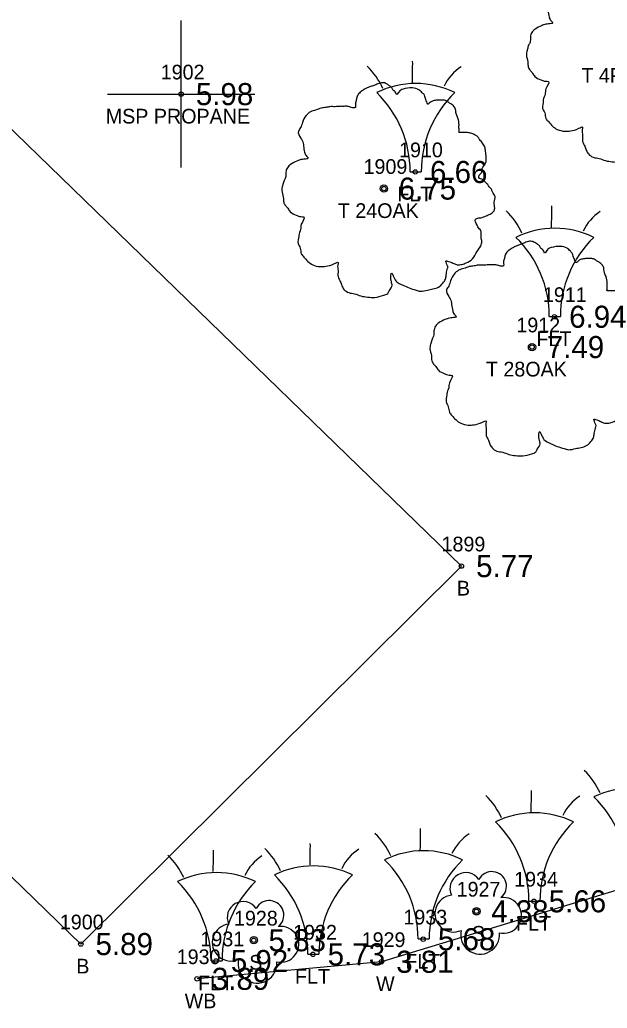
# Model space of a CAD drawing. Extents: x 2608598 to 2610682, y 641451 to 643526.
# Drawn here: x 2609191.3 to 2609231.3, y 642871.7 to 642938.9 of the extents above; entities that cross this region are included whole.
import ezdxf

# ---------------------------------------------------------------- set-up
doc = ezdxf.new("R2010")
doc.units = 0
for name, color, linetype in [('RD_EX_Bldg', 7, 'Continuous'), ('RD_EX_Bldg_txCode', 7, 'Continuous'), ('RD_EX_BldgApp', 7, 'Continuous'), ('RD_EX_BldgApp_txCode', 7, 'Continuous'), ('RD_EX_Misc', 7, 'Continuous'), ('RD_EX_Misc_txCode', 7, 'Continuous'), ('RD_EX_TX_Bldg_ELEV', 7, 'Continuous'), ('RD_EX_TX_BldgApp_ELEV', 7, 'Continuous'), ('RD_EX_TX_Misc_ELEV', 7, 'Continuous'), ('RD_EX_TX_VEG_ELEV', 7, 'Continuous'), ('RD_EX_VEG', 7, 'Continuous'), ('RD_EX_VEG_txCode', 7, 'Continuous'), ('RD_SMD_Locator', 7, 'Continuous')]:
    doc.layers.add(name, color=color, linetype=linetype)

msp = doc.modelspace()

# ---------------------------------------------------------------- linework, layer by layer
at = {"layer": 'RD_EX_Bldg'}
msp.add_lwpolyline([(2609131.739, 642937.949), (2609157.607, 642963.648), (2609221.367, 642901.728), (2609195.499, 642876.028), (2609131.739, 642937.949)], dxfattribs=at)
at = {"layer": 'RD_EX_BldgApp'}
for p, q in [((2609217.887, 642928.548), (2609218.637, 642928.548)), ((2609227.343, 642918.704), (2609228.093, 642918.704)), ((2609225.957, 642878.955), (2609226.707, 642878.955)), ((2609218.424, 642876.377), (2609219.174, 642876.377)), ((2609210.931, 642875.348), (2609211.681, 642875.348)), ((2609204.348, 642874.893), (2609205.098, 642874.893))]:
    msp.add_line(p, q, dxfattribs=at)
msp.add_lwpolyline([(2609259.329, 642906.089), (2609262.471, 642891.581), (2609238.117, 642881.572), (2609215.937, 642874.826), (2609203.404, 642873.665)], dxfattribs=at)
for centre, radius, start, end in [((2609211.569, 642932.191), 4.895, 24.32791, 46.26654), ((2609180.18, 642935.886), 37.876, 358.06712, 0.27154), ((2609223.15, 642932.941), 3.283, 123.29064, 154.48862), ((2609218.262, 642928.548), 5.997, 63.77943, 116.22057), ((2609210.387, 642928.548), 7.5, 0, 45.83662), ((2609226.137, 642928.548), 7.5, 134.16338, 180), ((2609221.026, 642922.347), 4.895, 24.32791, 46.26654), ((2609189.637, 642926.042), 37.876, 358.06712, 0.27154), ((2609232.607, 642923.097), 3.283, 123.29064, 154.48862), ((2609227.718, 642918.704), 5.997, 63.77943, 116.22057), ((2609219.843, 642918.704), 7.5, 0, 45.83662), ((2609235.593, 642918.704), 7.5, 134.16338, 180), ((2609226.338, 642884.294), 4.895, 24.32791, 46.26654), ((2609233.03, 642880.651), 5.997, 63.77943, 116.22057), ((2609219.639, 642882.597), 4.895, 24.32791, 46.26654), ((2609188.25, 642886.293), 37.876, 358.06712, 0.27154), ((2609231.22, 642883.348), 3.283, 123.29064, 154.48862), ((2609225.155, 642880.651), 7.5, 0, 45.83662), ((2609226.332, 642878.955), 5.997, 63.77943, 116.22057), ((2609218.457, 642878.955), 7.5, 0, 45.83662), ((2609234.207, 642878.955), 7.5, 134.16338, 180), ((2609212.106, 642880.019), 4.895, 24.32791, 46.26654), ((2609180.717, 642883.715), 37.876, 358.06712, 0.27154), ((2609223.687, 642880.77), 3.283, 123.29064, 154.48862), ((2609173.224, 642882.686), 37.876, 358.06712, 0.27154), ((2609198.03, 642878.536), 4.895, 24.32791, 46.26654), ((2609166.641, 642882.231), 37.876, 358.06712, 0.27154), ((2609209.611, 642879.286), 3.283, 123.29064, 154.48862), ((2609204.613, 642878.991), 4.895, 24.32791, 46.26654), ((2609216.194, 642879.741), 3.283, 123.29064, 154.48862), ((2609218.799, 642876.377), 5.997, 63.77943, 116.22057), ((2609211.306, 642875.348), 5.997, 63.77943, 116.22057), ((2609210.924, 642876.377), 7.5, 0, 45.83662), ((2609226.674, 642876.377), 7.5, 134.16338, 180), ((2609204.723, 642874.893), 5.997, 63.77943, 116.22057), ((2609203.431, 642875.348), 7.5, 0, 45.83662), ((2609219.181, 642875.348), 7.5, 134.16338, 180), ((2609196.848, 642874.893), 7.5, 0, 45.83662), ((2609212.598, 642874.893), 7.5, 134.16338, 180)]:
    msp.add_arc(centre, radius, start, end, dxfattribs=at)
at = {"layer": 'RD_EX_Misc'}
for p, q in [((2609202.317, 642928.823), (2609202.317, 642938.823)), ((2609197.317, 642933.823), (2609207.317, 642933.823))]:
    msp.add_line(p, q, dxfattribs=at)
at = {"layer": 'RD_EX_VEG'}
for centre, radius in [((2609216.103, 642927.4), 0.25), ((2609216.09, 642927.381), 0.0001), ((2609226.169, 642916.623), 0.25), ((2609226.156, 642916.604), 0.0001), ((2609222.392, 642878.257), 0.25), ((2609207.256, 642876.289), 0.25)]:
    msp.add_circle(centre, radius, dxfattribs=at)
for centre, radius, start, end in [((2609221.671, 642879.804), 1.084, 34.97629, 204.75602), ((2609223.437, 642879.959), 0.995, 308.76261, 152.04674), ((2609220.828, 642878.101), 1.257, 96.45179, 294.73401), ((2609206.535, 642877.836), 1.084, 34.97629, 204.75602), ((2609208.302, 642877.991), 0.995, 308.76261, 152.04674), ((2609224.231, 642877.978), 1.218, 256.56668, 98.10463), ((2609205.693, 642876.133), 1.257, 96.45179, 294.73401), ((2609209.096, 642876.01), 1.218, 256.56668, 98.10463), ((2609222.637, 642876.661), 1.318, 166.88266, 5.75893), ((2609207.502, 642874.693), 1.318, 166.88266, 5.75893)]:
    msp.add_arc(centre, radius, start, end, dxfattribs=at)
for points in [[(2609232.857, 642943.771), (2609232.557, 642943.796), (2609232.232, 642943.696), (2609231.982, 642943.596), (2609231.757, 642943.521), (2609231.532, 642943.421), (2609231.232, 642943.246), (2609231.008, 642943.046), (2609230.883, 642942.796), (2609230.833, 642942.571), (2609230.783, 642942.296), (2609230.783, 642942.121), (2609230.658, 642942.096), (2609230.508, 642942.121), (2609230.258, 642942.196), (2609230.008, 642942.196), (2609229.758, 642942.196), (2609229.408, 642942.171), (2609229.058, 642942.171), (2609228.784, 642942.121), (2609228.459, 642942.071), (2609228.084, 642941.946), (2609227.734, 642941.821), (2609227.434, 642941.572), (2609227.184, 642941.097), (2609227.059, 642940.747), (2609226.909, 642940.497), (2609227.059, 642940.047), (2609227.234, 642939.697), (2609227.259, 642939.497), (2609227.334, 642939.073), (2609227.434, 642938.848), (2609227.559, 642938.648), (2609227.484, 642938.623), (2609227.109, 642938.573), (2609226.809, 642938.473), (2609226.385, 642938.248), (2609226.16, 642938.023), (2609226.06, 642937.698), (2609226.035, 642937.348), (2609225.935, 642937.149), (2609225.86, 642936.874), (2609225.835, 642936.799), (2609225.785, 642936.474), (2609225.885, 642936.024), (2609225.91, 642935.674), (2609226.035, 642935.449), (2609226.185, 642935.274), (2609226.36, 642935.024), (2609226.759, 642934.8), (2609227.084, 642934.7), (2609227.284, 642934.675), (2609227.109, 642934.175), (2609227.059, 642933.825), (2609226.934, 642933.425), (2609226.934, 642933.35), (2609226.884, 642932.875), (2609227.034, 642932.55), (2609227.109, 642932.176), (2609227.284, 642931.951), (2609227.559, 642931.651), (2609227.884, 642931.426), (2609228.384, 642931.301), (2609228.784, 642931.326), (2609229.358, 642931.501), (2609229.608, 642931.576), (2609229.583, 642931.401), (2609229.608, 642931.026), (2609229.608, 642930.601), (2609229.758, 642930.277), (2609229.858, 642930.002), (2609230.008, 642929.752), (2609230.333, 642929.527), (2609230.733, 642929.452), (2609231.157, 642929.302), (2609231.607, 642929.227), (2609232.107, 642929.202), (2609232.707, 642929.352), (2609232.982, 642929.477), (2609233.082, 642929.652), (2609233.282, 642930.027), (2609233.232, 642930.252), (2609233.257, 642930.851), (2609233.356, 642930.676), (2609233.531, 642930.326), (2609234.031, 642930.027), (2609234.431, 642929.852), (2609234.906, 642929.702), (2609235.206, 642929.627), (2609235.68, 642929.702), (2609236.055, 642929.777), (2609236.43, 642929.902), (2609236.73, 642930.177), (2609236.905, 642930.451), (2609236.955, 642930.726), (2609237.03, 642931.101), (2609237.08, 642931.276)], [(2609216.234, 642934.567), (2609215.935, 642934.592), (2609215.61, 642934.492), (2609215.36, 642934.392), (2609215.135, 642934.317), (2609214.91, 642934.217), (2609214.61, 642934.042), (2609214.385, 642933.842), (2609214.26, 642933.592), (2609214.21, 642933.367), (2609214.16, 642933.092), (2609214.16, 642932.917), (2609214.035, 642932.892), (2609213.885, 642932.917), (2609213.636, 642932.992), (2609213.386, 642932.992), (2609213.136, 642932.992), (2609212.786, 642932.967), (2609212.436, 642932.967), (2609212.161, 642932.917), (2609211.836, 642932.868), (2609211.462, 642932.743), (2609211.112, 642932.618), (2609210.812, 642932.368), (2609210.562, 642931.893), (2609210.437, 642931.543), (2609210.287, 642931.293), (2609210.437, 642930.843), (2609210.612, 642930.494), (2609210.637, 642930.294), (2609210.712, 642929.869), (2609210.812, 642929.644), (2609210.937, 642929.444), (2609210.862, 642929.419), (2609210.487, 642929.369), (2609210.187, 642929.269), (2609209.762, 642929.044), (2609209.537, 642928.819), (2609209.437, 642928.494), (2609209.412, 642928.145), (2609209.313, 642927.945), (2609209.238, 642927.67), (2609209.213, 642927.595), (2609209.163, 642927.27), (2609209.263, 642926.82), (2609209.288, 642926.47), (2609209.412, 642926.245), (2609209.562, 642926.071), (2609209.737, 642925.821), (2609210.137, 642925.596), (2609210.462, 642925.496), (2609210.662, 642925.471), (2609210.487, 642924.971), (2609210.437, 642924.621), (2609210.312, 642924.221), (2609210.312, 642924.146), (2609210.262, 642923.672), (2609210.412, 642923.347), (2609210.487, 642922.972), (2609210.662, 642922.747), (2609210.937, 642922.447), (2609211.262, 642922.222), (2609211.761, 642922.097), (2609212.161, 642922.122), (2609212.736, 642922.297), (2609212.986, 642922.372), (2609212.961, 642922.197), (2609212.986, 642921.822), (2609212.986, 642921.398), (2609213.136, 642921.073), (2609213.236, 642920.798), (2609213.386, 642920.548), (2609213.711, 642920.323), (2609214.11, 642920.248), (2609214.535, 642920.098), (2609214.985, 642920.023), (2609215.485, 642919.998), (2609216.085, 642920.148), (2609216.359, 642920.273), (2609216.459, 642920.448), (2609216.659, 642920.823), (2609216.609, 642921.048), (2609216.634, 642921.647), (2609216.734, 642921.472), (2609216.909, 642921.123), (2609217.409, 642920.823), (2609217.809, 642920.648), (2609218.284, 642920.498), (2609218.583, 642920.423), (2609219.058, 642920.498), (2609219.433, 642920.573), (2609219.808, 642920.698), (2609220.108, 642920.973), (2609220.283, 642921.248), (2609220.333, 642921.522), (2609220.408, 642921.897), (2609220.458, 642922.072)], [(2609220.458, 642922.072), (2609220.383, 642922.247), (2609220.333, 642922.497), (2609220.408, 642922.472), (2609220.583, 642922.422), (2609220.857, 642922.297), (2609221.082, 642922.222), (2609221.407, 642922.247), (2609221.682, 642922.347), (2609222.132, 642922.622), (2609222.407, 642923.097), (2609222.682, 642923.497), (2609222.757, 642923.821), (2609222.707, 642924.046), (2609222.682, 642924.546), (2609222.482, 642924.796), (2609222.432, 642924.921), (2609222.332, 642925.321), (2609222.407, 642925.371), (2609222.682, 642925.421), (2609223.056, 642925.546), (2609223.331, 642925.671), (2609223.556, 642925.846), (2609223.631, 642926.071), (2609223.606, 642926.47), (2609223.656, 642926.87), (2609223.581, 642927.02), (2609223.481, 642927.17), (2609223.406, 642927.37), (2609223.256, 642927.52), (2609223.156, 642927.67), (2609223.056, 642927.77), (2609222.932, 642927.92), (2609222.757, 642928.045), (2609222.607, 642928.095), (2609222.557, 642928.245), (2609222.707, 642928.444), (2609222.757, 642928.544), (2609222.782, 642928.769), (2609223.007, 642929.119), (2609223.056, 642929.519), (2609223.007, 642929.944), (2609222.957, 642930.219), (2609222.807, 642930.494), (2609222.607, 642930.743), (2609222.482, 642930.918), (2609222.307, 642931.043), (2609221.982, 642931.168), (2609221.732, 642931.218), (2609221.382, 642931.218), (2609221.182, 642931.268), (2609221.207, 642931.318), (2609221.207, 642931.468), (2609221.207, 642931.743), (2609221.132, 642932.193), (2609220.982, 642932.693), (2609220.982, 642932.718), (2609220.882, 642932.967), (2609220.658, 642933.167), (2609220.483, 642933.267), (2609220.283, 642933.392), (2609220.033, 642933.417), (2609219.733, 642933.417), (2609219.458, 642933.367), (2609219.258, 642933.267), (2609219.083, 642933.142), (2609219.008, 642933.292), (2609218.908, 642933.592), (2609218.858, 642933.742), (2609218.708, 642933.917), (2609218.484, 642934.117), (2609218.034, 642934.242), (2609217.409, 642934.167), (2609217.109, 642933.967), (2609216.959, 642933.792), (2609216.909, 642933.917), (2609216.709, 642934.117), (2609216.609, 642934.292), (2609216.434, 642934.417), (2609216.284, 642934.517), (2609216.184, 642934.567)], [(2609226.301, 642923.79), (2609226.001, 642923.815), (2609225.676, 642923.715), (2609225.426, 642923.615), (2609225.201, 642923.54), (2609224.976, 642923.44), (2609224.676, 642923.265), (2609224.451, 642923.065), (2609224.326, 642922.815), (2609224.276, 642922.59), (2609224.227, 642922.316), (2609224.227, 642922.141), (2609224.102, 642922.116), (2609223.952, 642922.141), (2609223.702, 642922.216), (2609223.452, 642922.216), (2609223.202, 642922.216), (2609222.852, 642922.191), (2609222.502, 642922.191), (2609222.227, 642922.141), (2609221.903, 642922.091), (2609221.528, 642921.966), (2609221.178, 642921.841), (2609220.878, 642921.591), (2609220.628, 642921.116), (2609220.503, 642920.766), (2609220.353, 642920.516), (2609220.503, 642920.067), (2609220.678, 642919.717), (2609220.703, 642919.517), (2609220.778, 642919.092), (2609220.878, 642918.867), (2609221.003, 642918.667), (2609220.928, 642918.642), (2609220.553, 642918.592), (2609220.253, 642918.492), (2609219.828, 642918.267), (2609219.604, 642918.042), (2609219.504, 642917.718), (2609219.479, 642917.368), (2609219.379, 642917.168), (2609219.304, 642916.893), (2609219.279, 642916.818), (2609219.229, 642916.493), (2609219.329, 642916.043), (2609219.354, 642915.693), (2609219.479, 642915.469), (2609219.629, 642915.294), (2609219.803, 642915.044), (2609220.203, 642914.819), (2609220.528, 642914.719), (2609220.728, 642914.694), (2609220.553, 642914.194), (2609220.503, 642913.844), (2609220.378, 642913.444), (2609220.378, 642913.37), (2609220.328, 642912.895), (2609220.478, 642912.57), (2609220.553, 642912.195), (2609220.728, 642911.97), (2609221.003, 642911.67), (2609221.328, 642911.445), (2609221.828, 642911.32), (2609222.227, 642911.345), (2609222.802, 642911.52), (2609223.052, 642911.595), (2609223.027, 642911.42), (2609223.052, 642911.045), (2609223.052, 642910.621), (2609223.202, 642910.296), (2609223.302, 642910.021), (2609223.452, 642909.771), (2609223.777, 642909.546), (2609224.177, 642909.471), (2609224.601, 642909.321), (2609225.051, 642909.246), (2609225.551, 642909.221), (2609226.151, 642909.371), (2609226.426, 642909.496), (2609226.526, 642909.671), (2609226.725, 642910.046), (2609226.675, 642910.271), (2609226.7, 642910.871), (2609226.8, 642910.696), (2609226.975, 642910.346), (2609227.475, 642910.046), (2609227.875, 642909.871), (2609228.35, 642909.721), (2609228.65, 642909.646), (2609229.124, 642909.721), (2609229.499, 642909.796), (2609229.874, 642909.921), (2609230.174, 642910.196), (2609230.349, 642910.471), (2609230.399, 642910.746), (2609230.474, 642911.12), (2609230.524, 642911.295)], [(2609230.524, 642911.295), (2609230.449, 642911.47), (2609230.399, 642911.72), (2609230.474, 642911.695), (2609230.649, 642911.645), (2609230.924, 642911.52), (2609231.149, 642911.445), (2609231.473, 642911.47), (2609231.748, 642911.57), (2609232.198, 642911.845), (2609232.473, 642912.32), (2609232.748, 642912.72), (2609232.823, 642913.045), (2609232.773, 642913.27), (2609232.748, 642913.769), (2609232.548, 642914.019), (2609232.498, 642914.144), (2609232.398, 642914.544), (2609232.473, 642914.594), (2609232.748, 642914.644), (2609233.123, 642914.769), (2609233.398, 642914.894), (2609233.622, 642915.069), (2609233.697, 642915.294), (2609233.672, 642915.693), (2609233.722, 642916.093), (2609233.647, 642916.243), (2609233.547, 642916.393), (2609233.472, 642916.593), (2609233.323, 642916.743), (2609233.223, 642916.893), (2609233.123, 642916.993), (2609232.998, 642917.143), (2609232.823, 642917.268), (2609232.673, 642917.318), (2609232.623, 642917.468), (2609232.773, 642917.668), (2609232.823, 642917.768), (2609232.848, 642917.992), (2609233.073, 642918.342), (2609233.123, 642918.742), (2609233.073, 642919.167), (2609233.023, 642919.442), (2609232.873, 642919.717), (2609232.673, 642919.967), (2609232.548, 642920.142), (2609232.373, 642920.266), (2609232.048, 642920.391), (2609231.798, 642920.441), (2609231.448, 642920.441), (2609231.248, 642920.491), (2609231.273, 642920.541), (2609231.273, 642920.691), (2609231.273, 642920.966), (2609231.198, 642921.416), (2609231.049, 642921.916), (2609231.049, 642921.941), (2609230.949, 642922.191), (2609230.724, 642922.391), (2609230.549, 642922.49), (2609230.349, 642922.615), (2609230.099, 642922.64), (2609229.799, 642922.64), (2609229.524, 642922.59), (2609229.324, 642922.49), (2609229.149, 642922.366), (2609229.074, 642922.515), (2609228.974, 642922.815), (2609228.924, 642922.965), (2609228.775, 642923.14), (2609228.55, 642923.34), (2609228.1, 642923.465), (2609227.475, 642923.39), (2609227.175, 642923.19), (2609227.025, 642923.015), (2609226.975, 642923.14), (2609226.775, 642923.34), (2609226.675, 642923.515), (2609226.501, 642923.64), (2609226.351, 642923.74), (2609226.251, 642923.79)]]:
    msp.add_spline(points, degree=3, dxfattribs=at)
at = {"layer": 'RD_SMD_Locator'}
for centre in [(2609202.317, 642933.823), (2609218.234, 642928.53), (2609216.103, 642927.4), (2609227.691, 642918.686), (2609226.169, 642916.623), (2609221.367, 642901.728), (2609226.304, 642878.937), (2609222.392, 642878.257), (2609195.499, 642876.028), (2609207.256, 642876.289), (2609218.771, 642876.359), (2609211.278, 642875.33), (2609204.695, 642874.875), (2609215.937, 642874.826), (2609203.404, 642873.665)]:
    msp.add_circle(centre, 0.15, dxfattribs=at)

# ---------------------------------------------------------------- texts
at = {"layer": 'RD_EX_Bldg_txCode'}
for s, p in [('1899', (2609220.02, 642902.728)), ('B', (2609221.06, 642899.728)), ('1900', (2609194.074, 642877.028)), ('B', (2609195.192, 642874.028))]:
    msp.add_text(s, height=1, dxfattribs=at).set_placement(p)
at = {"layer": 'RD_EX_BldgApp_txCode'}
for s, p in [('1910', (2609217.132, 642929.53)), ('FLT', (2609217.014, 642926.53)), ('1911', (2609226.911, 642919.686)), ('FLT', (2609226.47, 642916.686)), ('1934', (2609224.957, 642879.937)), ('1933', (2609217.425, 642877.359)), ('FLT', (2609225.083, 642876.937)), ('1932', (2609209.932, 642876.33)), ('1931', (2609203.632, 642875.875)), ('FLT', (2609217.551, 642874.359)), ('FLT', (2609203.475, 642872.875)), ('FLT', (2609210.058, 642873.33))]:
    msp.add_text(s, height=1, dxfattribs=at).set_placement(p)
at = {"layer": 'RD_EX_Misc_txCode'}
for s, p in [('1902', (2609200.931, 642934.823)), ('MSP PROPANE', (2609197.195, 642931.823)), ('1929', (2609214.591, 642875.826)), ('1930', (2609202.018, 642874.665)), ('W', (2609215.567, 642872.826)), ('WB', (2609202.561, 642871.665))]:
    msp.add_text(s, height=1, dxfattribs=at).set_placement(p)
at = {"layer": 'RD_EX_TX_Bldg_ELEV'}
for s, p in [('5.77', (2609222.367, 642900.978)), ('5.89', (2609196.499, 642875.278))]:
    msp.add_text(s, height=1.5, dxfattribs=at).set_placement(p)
at = {"layer": 'RD_EX_TX_BldgApp_ELEV'}
for s, p in [('6.66', (2609219.234, 642927.78)), ('6.94', (2609228.691, 642917.936)), ('5.66', (2609227.304, 642878.187)), ('5.68', (2609219.771, 642875.609)), ('5.73', (2609212.278, 642874.58)), ('5.92', (2609205.695, 642874.125))]:
    msp.add_text(s, height=1.5, dxfattribs=at).set_placement(p)
at = {"layer": 'RD_EX_TX_Misc_ELEV'}
for s, p in [('5.98', (2609203.317, 642933.073)), ('3.81', (2609216.937, 642874.076)), ('3.89', (2609204.404, 642872.915))]:
    msp.add_text(s, height=1.5, dxfattribs=at).set_placement(p)
at = {"layer": 'RD_EX_TX_VEG_ELEV'}
for s, p in [('6.75', (2609217.103, 642926.65)), ('7.49', (2609227.169, 642915.873)), ('4.38', (2609223.392, 642877.507)), ('5.83', (2609208.256, 642875.539))]:
    msp.add_text(s, height=1.5, dxfattribs=at).set_placement(p)
at = {"layer": 'RD_EX_VEG_txCode'}
for s, p in [('T 4PLUM', (2609229.528, 642934.603)), ('1909', (2609214.717, 642928.4)), ('T 24OAK', (2609212.969, 642925.4)), ('1912', (2609225.106, 642917.623)), ('T 28OAK', (2609223.035, 642914.623)), ('1927', (2609221.045, 642879.257)), ('1928', (2609205.91, 642877.289)), ('S', (2609222.085, 642876.257)), ('S', (2609206.949, 642874.289))]:
    msp.add_text(s, height=1, dxfattribs=at).set_placement(p)

doc.saveas('drawing.dxf')
